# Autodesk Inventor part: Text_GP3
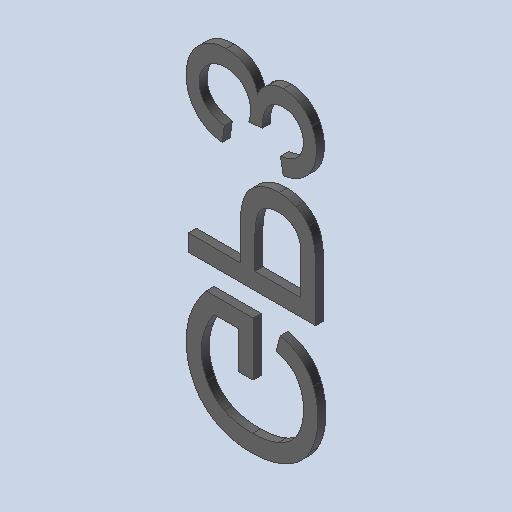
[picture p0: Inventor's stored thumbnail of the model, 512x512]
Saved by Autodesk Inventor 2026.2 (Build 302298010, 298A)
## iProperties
Created: 2026-10
Part Number: Text_GP3
Material: Générique
Document SubType Name: Modeling
Designer: mel
Density: 1 g/cm^3
Appearance: Par défaut
Author: mel
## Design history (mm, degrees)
feature "Base1"
feature "Base2"
feature "Base3"
node "Solide1"
node "Solide2"
node "Solide3"
